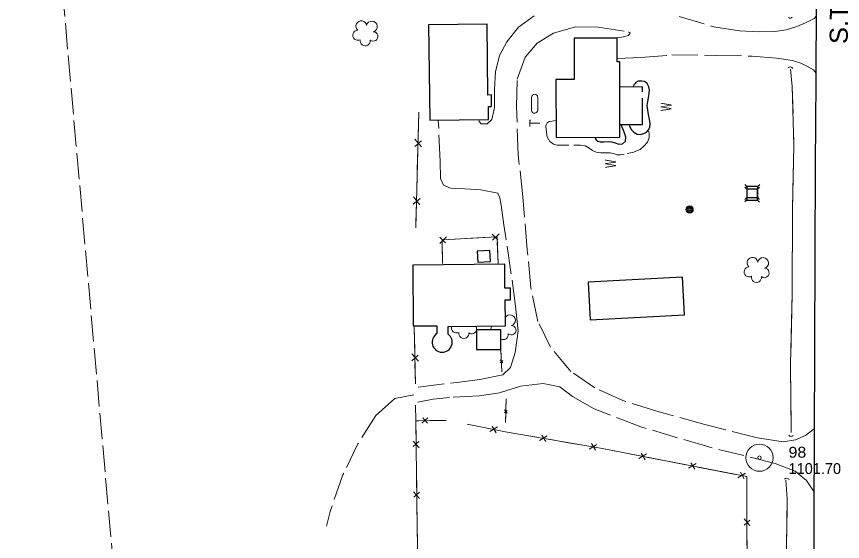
# Model space of a CAD drawing. Extents: x 296583 to 298831, y 44522 to 45957.
# Drawn here: x 297236.9 to 297692.9, y 45265.7 to 45555.3 of the extents above; entities that cross this region are included whole.
import ezdxf

# ---------------------------------------------------------------- set-up
doc = ezdxf.new("R2010")
doc.units = 0
doc.header["$LTSCALE"] = 2.4
doc.linetypes.add('LONG_DASHED', pattern=[7.5, 6, -1.5])
doc.linetypes.add('SHORT_DASHED', pattern=[2.7, 1.5, -1.2])
for name, color, linetype, lineweight in [('11', 7, 'Continuous', 25), ('12', 7, 'Continuous', 25), ('14', 7, 'Continuous', 13), ('15', 7, 'Continuous', 13), ('17', 7, 'LONG_DASHED', 13), ('18', 7, 'Continuous', 13), ('19', 7, 'Continuous', 13), ('21', 7, 'Continuous', 25), ('4', 7, 'Continuous', 13), ('6', 7, 'Continuous', 13)]:
    doc.layers.add(name, color=color, linetype=linetype, lineweight=lineweight)

msp = doc.modelspace()

# ---------------------------------------------------------------- linework, layer by layer
at = {"layer": '11'}
msp.add_lwpolyline([(297677.324, 45228.283), (297677.318, 45281.197), (297677.332, 45323.688), (297677.669, 45372.563), (297677.785, 45423.877), (297677.961, 45473.565), (297678.391, 45519.767), (297678.595, 45564.143), (297678.918, 45607.954), (297680.057, 45662.442), (297681.8, 45714.535), (297683.993, 45772.961), (297685.684, 45810.311), (297686.569, 45830.443)], dxfattribs=at)
at = {"layer": '12', "lineweight": 13}
for p, q in [((297521.202, 45510.665), (297521.184, 45503.568)), ((297524.68, 45503.655), (297524.703, 45510.678))]:
    msp.add_line(p, q, dxfattribs=at)
at = {"layer": '12'}
for points in [[(297465.025, 45498.099), (297497.541, 45498.471), (297497.459, 45505.65), (297499.193, 45505.67), (297499.12, 45511.997), (297497.176, 45511.975), (297496.729, 45551.094), (297464.423, 45550.724)], [(297570.049, 45488.671), (297569.895, 45530.287), (297568.485, 45530.282), (297568.436, 45543.377), (297544.738, 45543.289), (297544.822, 45520.517), (297534.717, 45520.479), (297534.836, 45488.541)], [(297498.208, 45426.157), (297491.185, 45425.786), (297491.498, 45419.86), (297498.521, 45420.231)], [(297553.607, 45387.989), (297605.69, 45390.765), (297604.585, 45411.499), (297552.502, 45408.723)], [(297490.816, 45371.601), (297504.304, 45371.575), (297504.325, 45382.524), (297490.837, 45382.55)]]:
    msp.add_lwpolyline(points, close=True, dxfattribs=at)
at = {"layer": '12', "linetype": 'LONG_DASHED'}
msp.add_lwpolyline([(297570.023, 45495.65), (297582.478, 45495.805), (297582.461, 45516.418), (297569.947, 45516.268)], dxfattribs=at)
at = {"layer": '12'}
msp.add_lwpolyline([(297475.154, 45380.149), (297475.116, 45384.34), (297506.8, 45384.623), (297506.784, 45386.41), (297506.671, 45399.033), (297509.694, 45399.06), (297509.667, 45402.043), (297509.637, 45405.397), (297506.527, 45405.369), (297506.408, 45418.621), (297455.657, 45418.167), (297455.958, 45384.591), (297468.942, 45384.707), (297468.98, 45380.384)], dxfattribs=at)
at = {"layer": '12', "lineweight": 13}
for centre, start, end in [((297522.953, 45510.66), 0.57588, 179.82657), ((297522.93, 45503.672), 183.39403, 359.44135)]:
    msp.add_arc(centre, 1.75, start, end, dxfattribs=at)
at = {"layer": '12'}
msp.add_arc((297471.892, 45375.661), 5.548, 121.65689, 53.98695, dxfattribs=at)
at = {"layer": '14'}
for centre, radius in [((297608.495, 45448.852), 2.018), ((297608.482, 45448.849), 1.518), ((297608.522, 45448.855), 1.008), ((297608.512, 45448.859), 0.502)]:
    msp.add_circle(centre, radius, dxfattribs=at)
at = {"layer": '15'}
for p, q in [((297457.335, 45438.754), (297458.978, 45502.552)), ((297458.644, 45489.59), (297458.978, 45502.552)), ((297456.772, 45483.621), (297460.485, 45486.728)), ((297460.475, 45483.33), (297456.876, 45487.682)), ((297458.156, 45470.653), (297458.45, 45482.054)), ((297457.823, 45457.691), (297458.156, 45470.653)), ((297455.95, 45451.722), (297459.664, 45454.829)), ((297459.654, 45451.431), (297456.055, 45455.783)), ((297457.335, 45438.754), (297457.629, 45450.155)), ((297470.539, 45433.542), (297473.646, 45430.408)), ((297470.559, 45430.156), (297474.236, 45433.759)), ((297476.104, 45432.299), (297487.904, 45432.989)), ((297487.904, 45432.989), (297498.282, 45433.595)), ((297499.577, 45435.24), (297502.685, 45432.105)), ((297499.597, 45431.853), (297503.274, 45435.456)), ((297472.049, 45418.968), (297471.955, 45429.363)), ((297502.278, 45430.839), (297502.733, 45419.028)), ((297457.085, 45352.637), (297456.506, 45384.035)), ((297456.741, 45371.276), (297456.506, 45384.035)), ((297458.814, 45365.202), (297455.086, 45369.324)), ((297455.16, 45365.326), (297458.676, 45368.543)), ((297504.837, 45359.245), (297504.291, 45371.737)), ((297504.513, 45366.661), (297504.298, 45371.575)), ((297457.085, 45352.637), (297456.878, 45363.858)), ((297505.399, 45364.264), (297503.874, 45365.867)), ((297503.943, 45364.277), (297505.31, 45365.592)), ((297504.837, 45359.245), (297504.642, 45363.71)), ((297506.942, 45331.333), (297507.164, 45344.395)), ((297507.074, 45339.087), (297507.164, 45344.395)), ((297506.329, 45336.637), (297507.838, 45337.922)), ((297507.846, 45336.531), (297506.357, 45338.3)), ((297506.942, 45331.333), (297507.021, 45336.001)), ((297457.426, 45332.288), (297457.546, 45322.29)), ((297463.969, 45333.966), (297460.653, 45330.982)), ((297463.862, 45331.033), (297461.287, 45333.862)), ((297474.053, 45332.552), (297465.044, 45332.409)), ((297496.788, 45328.248), (297485.682, 45330.454)), ((297502.447, 45328.897), (297498.169, 45326.444)), ((297501.649, 45325.752), (297499.524, 45329.408)), ((297524.196, 45323.223), (297513.039, 45325.155)), ((297529.836, 45324.011), (297525.62, 45321.454)), ((297529.116, 45320.848), (297526.902, 45324.451)), ((297540.496, 45320.4), (297530.683, 45322.099)), ((297455.813, 45321.105), (297459.11, 45317.412)), ((297459.068, 45320.973), (297455.917, 45318.128)), ((297551.653, 45318.467), (297540.496, 45320.4)), ((297557.294, 45319.256), (297553.078, 45316.698)), ((297556.573, 45316.092), (297554.359, 45319.695)), ((297457.625, 45315.682), (297457.761, 45304.315)), ((297579.039, 45313.319), (297567.922, 45315.472)), ((297584.694, 45313.995), (297580.428, 45311.521)), ((297583.911, 45310.847), (297581.768, 45314.492)), ((297595.279, 45310.172), (297585.502, 45312.067)), ((297606.396, 45308.019), (297595.279, 45310.172)), ((297612.051, 45308.695), (297607.785, 45306.222)), ((297611.268, 45305.547), (297609.126, 45309.192)), ((297457.761, 45304.315), (297457.88, 45294.317)), ((297622.637, 45304.873), (297612.86, 45306.767)), ((297633.754, 45302.719), (297622.637, 45304.873)), ((297638.626, 45300.247), (297636.484, 45303.893)), ((297639.409, 45303.395), (297635.143, 45300.922)), ((297640.01, 45291.311), (297639.98, 45301.27)), ((297456.148, 45293.131), (297459.445, 45289.438)), ((297459.402, 45293), (297456.252, 45290.154)), ((297640.044, 45279.988), (297640.01, 45291.311)), ((297457.959, 45287.708), (297458.095, 45276.341)), ((297641.8, 45274.57), (297638.549, 45278.278)), ((297638.559, 45274.73), (297641.723, 45277.536)), ((297640.094, 45263.445), (297640.064, 45273.404))]:
    msp.add_line(p, q, dxfattribs=at)
at = {"layer": '15', "lineweight": 25}
for points in [[(297575.105, 45495.254), (297576.39, 45492.837), (297577.711, 45491.438), (297579.593, 45490.41), (297581.121, 45490.285), (297583.208, 45490.688), (297584.745, 45491.549), (297585.809, 45492.753), (297586.445, 45494.118), (297586.749, 45495.998), (297586.366, 45498.746), (297585.838, 45501.268), (297585.365, 45503.555), (297585.125, 45506.216), (297585.356, 45508.343), (297586.058, 45511.588), (297586.3, 45514.61), (297585.912, 45516.533), (297584.979, 45518.304), (297583.659, 45519.431), (297582.126, 45519.702), (297580.145, 45519.582), (297578.774, 45518.811), (297578.188, 45518.117), (297577.898, 45517.724), (297577.406, 45516.77)], [(297556.16, 45488.62), (297556.316, 45488.215), (297556.946, 45487.353), (297557.762, 45486.569), (297559.082, 45486.217), (297561.216, 45486.12), (297563.796, 45486.395), (297565.423, 45486.15), (297567.43, 45485.557), (297569.482, 45484.943), (297571.494, 45484.989), (297573.075, 45486.608), (297573.329, 45488.816), (297572.633, 45490.555), (297571.637, 45493.354), (297570.839, 45495.191), (297570.716, 45495.545)]]:
    msp.add_lwpolyline(points, dxfattribs=at)
at = {"layer": '15'}
for points in [[(297472.049, 45418.968), (297471.931, 45432.055), (297502.163, 45433.822), (297502.733, 45419.028)], [(297474.053, 45332.552), (297457.426, 45332.288), (297457.131, 45340.865)], [(297459.088, 45332.314), (297457.426, 45332.288), (297457.131, 45340.865)], [(297457.426, 45332.288), (297458.134, 45273.124), (297459.691, 45187.524), (297461.194, 45080.187), (297462.548, 44976.644), (297464.144, 44888.893), (297466.789, 44813.574), (297470.787, 44709.482), (297470.06, 44661.06)], [(297635.579, 44650.43), (297635.894, 44715.773), (297638.067, 44805.759), (297638.519, 44884.052), (297639.777, 44960.845), (297640.569, 45061.514), (297640.403, 45160.692), (297639.979, 45301.513), (297559.293, 45317.144), (297507.689, 45326.082), (297485.682, 45330.454)], [(297513.039, 45325.155), (297507.689, 45326.082), (297503.246, 45326.965)], [(297567.922, 45315.472), (297559.293, 45317.144), (297558.14, 45317.344)], [(297458.095, 45276.341), (297458.134, 45273.124), (297458.257, 45266.344)]]:
    msp.add_lwpolyline(points, dxfattribs=at)
for centre, radius, start, end in [((297664.092, 45555.599), 1.277, 220.30354, 326.5431), ((297664.093, 45525.838), 1.634, 31.23861, 137.47817), ((297664.558, 45325.144), 1.503, 212.48986, 318.72942), ((297662, 45298.966), 1.673, 30.1846, 136.42416)]:
    msp.add_arc(centre, radius, start, end, dxfattribs=at)
at = {"layer": '17'}
for points in [[(297492.144, 45498.409), (297492.261, 45497.426), (297493.425, 45496.018), (297496.701, 45496.018), (297499.285, 45498.42), (297500.858, 45505.158), (297500.798, 45515.212), (297501.247, 45524.708), (297503.554, 45533.736), (297507.646, 45541.243), (297513.988, 45549.38), (297522.671, 45555.645)], [(297602.708, 45555.307), (297621.88, 45549.662), (297636.044, 45547.367), (297646.485, 45546.744), (297655.538, 45547.04), (297661.843, 45547.955), (297667.699, 45549.77), (297672.495, 45551.753), (297677.156, 45554.105), (297678.556, 45555.63)], [(297677.362, 45327.978), (297672.369, 45324.212), (297666.866, 45321.743), (297660.14, 45320.757), (297645.955, 45322.848), (297616.95, 45330.224), (297590.451, 45337.537), (297571.603, 45343.406), (297556.179, 45350.487), (297542.985, 45359.529), (297531.73, 45372.84), (297524.737, 45387.099), (297520.792, 45405.729), (297518.89, 45426.602), (297516.476, 45455.852), (297513.877, 45478.953), (297512.894, 45505.652), (297513.323, 45520.807), (297517.773, 45532.922), (297524.269, 45540.508), (297533.254, 45546.092), (297545.399, 45549.501), (297558.051, 45549.478), (297574.828, 45546.868), (297575.573, 45546.138), (297574.799, 45544.823), (297572.045, 45544.051), (297567.654, 45543.374)], [(297568.478, 45532.169), (297581.491, 45532.601), (297598.628, 45534.106), (297622.714, 45533.834), (297642.96, 45533.433), (297656.443, 45532.248), (297665.338, 45531.092), (297669.849, 45529.618), (297673.624, 45527.788), (297676.788, 45525.807), (297678.411, 45524.061)], [(297458.62, 45350.89), (297479.929, 45353.453), (297492.746, 45355.017), (297505.435, 45357.593), (297509.606, 45361.655), (297512.198, 45370.031), (297513.846, 45381.878), (297512.361, 45395.575), (297509.848, 45414.314), (297505.907, 45440.369), (297504.55, 45451.317), (297503.746, 45455.188), (297502.629, 45457.806), (297493.312, 45459.623), (297484.404, 45460.223), (297476.523, 45460.67), (297472.64, 45462.174), (297470.935, 45465.89), (297470.808, 45475.586), (297469.753, 45498.153)], [(297677.322, 45292.809), (297673.051, 45299.401), (297666.674, 45304.585), (297655.788, 45308.726), (297619.031, 45317.873), (297581.608, 45328.979), (297555.879, 45338.922), (297543.873, 45345.774), (297536.863, 45351.092), (297527.591, 45352.905), (297515.065, 45351.348), (297503.604, 45347.658), (297492.345, 45346.116), (297476.011, 45345.139), (297466.99, 45344.267), (297458.432, 45342.602)], [(297456.336, 45346.586), (297445.766, 45344.617), (297435.234, 45335.2), (297425.419, 45319.551), (297417.096, 45302.452), (297409.991, 45282.231), (297408.076, 45274.265)]]:
    msp.add_lwpolyline(points, dxfattribs=at)
at = {"layer": '17', "linetype": 'SHORT_DASHED'}
msp.add_lwpolyline([(297585.569, 45492.481), (297586.227, 45491.198), (297586.097, 45488.299), (297585.175, 45485.97), (297583.194, 45483.689), (297581.22, 45481.894), (297577.602, 45480.494), (297572.377, 45479.29), (297570.053, 45479.032), (297568.38, 45479.045), (297566.938, 45479.531), (297564.682, 45480.01), (297561.528, 45480.136), (297559.422, 45480.074), (297556.837, 45480.473), (297554.871, 45481.449), (297553.041, 45482.615), (297550.764, 45483.89), (297548.216, 45484.33), (297538.723, 45484.341), (297535.181, 45484.372), (297533.31, 45484.889), (297531.343, 45486.352), (297530.518, 45487.587), (297529.932, 45488.997), (297529.424, 45491.448), (297529.087, 45494.67), (297529.225, 45495.628), (297529.802, 45496.625), (297530.952, 45497.391), (297532.496, 45497.623), (297533.619, 45497.788), (297534.801, 45497.905)], dxfattribs=at)
at = {"layer": '18'}
for centre, radius, start, end in [((297427.242, 45549.934), 2.974, 7.98733, 229.22121), ((297433.094, 45549.778), 2.975, 285.63814, 168.61141), ((297425.346, 45544.906), 2.777, 90.95822, 298.73121), ((297433.817, 45544.304), 2.611, 230.34337, 88.27598), ((297429.399, 45541.875), 2.783, 167.63523, 8.64628), ((297643.195, 45419.462), 2.974, 7.98733, 229.22121), ((297649.047, 45419.306), 2.975, 285.63814, 168.61141), ((297641.299, 45414.434), 2.777, 90.95822, 298.73121), ((297649.77, 45413.832), 2.611, 230.34337, 88.27598), ((297645.352, 45411.403), 2.783, 167.63523, 8.64628), ((297509.331, 45387.75), 2.975, 285.63814, 149.83987), ((297479.793, 45383.515), 2.777, 159.75903, 298.73121), ((297488.264, 45382.913), 2.611, 230.34337, 350.14309), ((297488.264, 45382.913), 2.611, 352.01989, 36.78258), ((297501.583, 45382.878), 2.777, 142.79843, 187.09672), ((297510.054, 45382.276), 2.611, 230.34337, 88.27598), ((297483.846, 45380.484), 2.783, 167.63523, 8.64628), ((297505.636, 45379.847), 2.783, 241.66472, 8.64627)]:
    msp.add_arc(centre, radius, start, end, dxfattribs=at)
at = {"layer": '19'}
for p, q in [((297665.726, 45497.047), (297665.678, 45498.716)), ((297665.869, 45492.038), (297665.822, 45493.707)), ((297666.013, 45487.028), (297665.965, 45488.698)), ((297665.541, 45459.475), (297666.076, 45483.689)), ((297665.211, 45430.246), (297665.22, 45431.916)), ((297665.186, 45425.235), (297665.194, 45426.905)), ((297665.16, 45420.224), (297665.168, 45421.894)), ((297664.278, 45368.451), (297664.838, 45392.665)), ((297664.211, 45358.43), (297664.197, 45360.1)), ((297664.255, 45353.419), (297664.24, 45355.089)), ((297664.495, 45325.858), (297664.284, 45350.078))]:
    msp.add_line(p, q, dxfattribs=at)
for points in [[(297664.495, 45325.858), (297664.166, 45363.601), (297665.07, 45402.695), (297665.307, 45448.892), (297666.09, 45484.318), (297665.163, 45516.743), (297664.201, 45526.222)], [(297665.583, 45502.056), (297665.163, 45516.743), (297664.201, 45526.222)], [(297665.237, 45435.257), (297665.307, 45448.892), (297665.541, 45459.475)], [(297664.838, 45392.665), (297665.07, 45402.695), (297665.143, 45416.883)], [(297664.167, 45363.441), (297664.166, 45363.601), (297664.201, 45365.111)], [(297637.022, 44785.424), (297636.698, 44801.791), (297641.15, 44847.674), (297645.424, 44876.366), (297648.541, 44913.442), (297652.967, 44947.856), (297656.52, 44971.259), (297660.168, 45012.052), (297660.349, 45046.158), (297661.101, 45098.817), (297661.419, 45158.422), (297662.261, 45209.566), (297661.996, 45263.55), (297662.357, 45289.249), (297661.583, 45299.637)], [(297662.066, 45268.503), (297662.357, 45289.249), (297661.583, 45299.637)]]:
    msp.add_lwpolyline(points, dxfattribs=at)
at = {"layer": '21'}
for p, q in [((297640.034, 45460.048), (297638.982, 45461.117)), ((297640.123, 45461.496), (297639.071, 45462.565)), ((297647.103, 45461.055), (297646.033, 45460.003)), ((297647.192, 45462.503), (297646.122, 45461.451)), ((297639.988, 45454.048), (297638.919, 45452.997)), ((297640.077, 45455.496), (297639.008, 45454.445)), ((297647.129, 45454.382), (297646.076, 45455.45)), ((297647.04, 45452.934), (297645.987, 45454.002))]:
    msp.add_line(p, q, dxfattribs=at)
for points in [[(297645.987, 45454.002), (297646.033, 45460.003), (297640.034, 45460.048), (297639.988, 45454.048)], [(297646.076, 45455.45), (297646.122, 45461.451), (297640.123, 45461.496), (297640.077, 45455.496)]]:
    msp.add_lwpolyline(points, close=True, dxfattribs=at)
at = {"layer": '4', "linetype": 'LONG_DASHED'}
msp.add_line((297342.991, 44658.77), (297236.947, 45856.087), dxfattribs=at)
at = {"layer": '6'}
for radius in [7.5, 0.96]:
    msp.add_circle((297647.061, 45311.952), radius, dxfattribs=at)

# ---------------------------------------------------------------- texts
at = {"layer": '11', "width": 1.05}
msp.add_text('S.T.H. 25', height=10, rotation=89.626, dxfattribs=at).set_placement((297695.769, 45540.099))
at = {"layer": '12', "width": 0.85}
msp.add_text('T', height=6, rotation=89.564, dxfattribs=at).set_placement((297525.962, 45494.337))
at = {"layer": '15', "width": 0.6}
for p in [(297598.457, 45503.136), (297567.792, 45471.769)]:
    msp.add_text('W', height=6, rotation=89.564, dxfattribs=at).set_placement(p)
at = {"layer": '6', "width": 1.1}
msp.add_text('98', height=6, dxfattribs=at).set_placement((297663.061, 45311.952))
at = {"layer": '6'}
msp.add_text('1101.70', height=6, dxfattribs=at).set_placement((297663.061, 45302.952))

doc.saveas('drawing.dxf')
